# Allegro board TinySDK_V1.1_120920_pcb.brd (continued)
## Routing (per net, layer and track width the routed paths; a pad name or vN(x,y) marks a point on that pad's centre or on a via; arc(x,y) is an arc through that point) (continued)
GND_EARTH: length 13.6
  TOP w0.559: LAN1.8 165.07,21.21 ; 165.07,21.21 165.05,21.21 163.7,19.86 ; 165.07,21.21 172.09,21.21 173.23,22.35 173.23,23.44 C21.2
VBAT: length 7.7
  TOP w0.508: BAT1.1 66.39,36.58 D1.2 64.08,36.68 R11.1
VDD_3.3V: length 869
  TOP w0.254: 62.99,80.52 62.74,80.77 U7.3 ; 167.75,38.5 167.76,38.48 U4.30 ; U4.23 173.32,34.63 173.57,34.89 ; U4.42 162.18,32.63 162.05,32.77 ; U7.9 63.24,77.48
  TOP w0.508: 62.99,80.52 64.39,80.52
  TOP w0.559: v1(157.99,28.96) 157.99,28.7 154.69,25.4 FB2.1 ; R60.1 v1(75.46,88.77) ; 18.01,48.13 R39.2 v1(16.89,48.13) ; 18.01,40.51 R66.1 v1(16.89,40.51) ; R23.1 v1(66.32,88.77) ; CON8.39 41.25,75.54 v1(41.66,75.95) 42.05,75.55 CON8.41 ; v1(144.02,69.6) 144.39,69.6 144.4,69.59 v1(148.98,69.59) ; v1(144.02,69.6) 144.02,70.87 v1(143.89,70.99) ; v1(144.02,69.6) 144.02,69.22 144.15,69.09 v1(144.15,64.9) v1(144.15,61.34) ; v1(88.9,45.72) 89.66,46.48 C28.1 89.92,47.37 90.44,47.89 91.81,47.89 92.2,47.5 U5.8 ; 63.24,77.48 63.25,77.47 63.25,75.82 C67.1 66.17,75.56 67.18,76.58 67.18,79.88 66.55,80.52 C62.2 ; R32.2 129.29,38.99 128.91,39.37 v1(128.91,39.62) 128.91,39.88 129.54,40.51 R127.2 ; v1(16.89,42.04) R65.1 18.01,42.04 ; v1(16.89,46.61) R40.2 18.01,46.61 ; CON8.52 46.45,84.33 46.45,84.33 47.24,84.33 v1(48.13,83.44) ; v1(127.76,21.08) 128.14,20.7 R49.2 ; U2.4 28.22,20.73 21.46,13.97 R4.1 ; R21.1 173.86,29.18 v1(173.48,29.57) ; v1(173.74,36.96) 174.24,36.45 C16.1 175.01,36.32 173.57,34.89 ; R10.1 v1(99.31,49.28) v1(99.31,46.48) 99.31,42.04 v1(97.41,40.13) ; R31.2 137.01,40.51 R128.2 v1(137.03,41.78) ; R14.2 v1(70.89,88.77) ; 18.01,45.09 R43.1 v1(16.89,45.09) ; v1(160.27,28.83) 160.27,28.96 160.3,28.98 R20.1 ; R34.1 v1(72.42,88.77) ; CON8.24 35.25,85.09 v1(35.25,85.09) ; C17.1 168.78,39.75 170.69,41.66 v1(170.69,43.05) ; C17.1 167.64,39.75 v1(167.13,40.26) ; C17.1 168.66,39.5 167.75,38.59 167.75,38.5 ; R13.2 v1(67.84,88.77) ; v1(62.27,93.94) 62.27,91.27 R27.1 v1(63.27,88.77) ; v1(47.12,29.84) 45.85,28.57 C68.1 45.72,26.92 43.05,26.92 ; FB5.1 151.51,40.39 v1(151.76,40.13) ; R35.2 v1(16.89,51.18) ; R133.2 v1(144.91,41.78) ; 162.05,32.77 161.35,33.46 v1(161.35,34.86) 160.91,35.31 C18.1 160.15,35.43 160.15,36.7 C15.1 161.04,38.86 v1(160.78,39.12) 160.53,39.12 159.92,39.73 R5.2 ; v1(68.58,33.27) 68.48,33.17 D1.1 ; R131.2 v1(141.86,41.78) ; R30.1 63.88,83.44 65.66,81.66 C62.2 ; 23.25,84.7 23.25,84.7 CON8.2 ; 23.25,84.7 23.25,83.19 ; 23.25,84.7 22.86,85.09 22.35,85.09 v2(21.84,85.6) ; J1.2 96.77,117.32 R118.2 ; C62.2 64.39,80.52 ; R28.1 v1(69.37,88.77) ; 18.01,43.56 R64.1 v1(16.89,43.56) ; R129.2 v1(140.34,41.78) ; R126.2 127.13,37.47 v1(126.75,37.08) 126.95,36.88 FB1.1 ; R18.2 v1(73.94,88.77) ; 18.01,49.66 R37.2 v1(16.89,49.66) ; R132.2 v1(143.38,41.78) ; R9.1 v1(99.31,50.8) ; R12.2 v1(64.8,88.77) ; R19.2 v1(76.99,88.77)
  TOP w0.762: J1.2 99.06,115.32 100.33,114.05 102.62,114.05 108.03,119.46 CON6.1 ; 50.17,82.3 50.17,81.7 D4.1 53,77.56 54.36,76.2 57.02,76.2 57.66,75.56 C67.1
  TOP w1.016: v1(48.13,83.44) 48.13,83.19 49.02,82.3 50.17,82.3 52.96,85.09 C79.1 v1(51.05,85.72) ; v1(78.49,116.46) 78.59,116.35 R108.2 R107.2 R134.2 R114.2 R119.2 61.21,107.57 54.3,100.65 54.3,97.58 SDIO.1 55.59,93.8 R75.2
  TOP w1.524: v2(32.51,29.21) C11.1 C10.1 28.24,30.91 28.24,29.04 28.22,29.02 U2.2 U2.4 ; v2(21.84,85.6) 21.84,89.28 20.45,90.68 v2(15.37,90.68)
  BOTTOM w0.559: 143.38,40.79 v1(143.38,41.78) ; v1(143.89,70.99) R73.2 R72.2 ; 140.34,40.92 v1(140.34,41.78) ; R71.2 R42.2 v1(144.15,64.9) ; 144.91,40.79 v1(144.91,41.78) ; v1(144.02,69.6) 144.15,69.47 R41.2 ; 137.03,40.79 v1(137.03,41.78) ; C27.1 147.34,67.94 v1(148.98,69.59) CON10.4 ; 141.9,40.79 141.86,40.83 v1(141.86,41.78) ; v1(170.69,43.05) 170.69,42.93 172.21,41.4 172.21,38.48 v1(173.74,36.96) 174.14,36.55 174.14,30.22 v1(173.48,29.57) ; v1(167.13,40.26) 165.99,39.12 v1(160.78,39.12) ; v1(35.25,85.09) 35.31,85.03 C144.1 ; 121.54,35.31 122.43,34.42 122.43,23.62 124.97,21.08 v1(127.76,21.08) ; R38.2 R74.2 144.27,61.47 v1(144.15,61.34) ; 128.91,39.24 v1(128.91,39.62) ; v1(161.35,34.86) 160.27,33.78 v1(160.27,28.83) 158.12,28.83 v1(157.99,28.96) ; v1(99.31,46.48) 89.66,46.48 v1(88.9,45.72) ; v1(63.27,88.77) v1(64.8,88.77) v1(66.32,88.77) v1(67.84,88.77) v1(69.37,88.77) v1(70.89,88.77) v1(72.42,88.77) v1(73.94,88.77) v1(75.46,88.77) v1(76.99,88.77) ; v1(62.27,93.94) 61.89,94.32 57.56,94.32 SDIO.1 ; C148.1 46.61,83.44 v1(48.13,83.44) ; v1(99.31,49.28) v1(99.31,50.8) ; C145.1 v1(41.66,75.95)
  BOTTOM w1.016: SDIO.1 55.44,96.44 51.78,96.44 51.05,95.72 v1(51.05,85.72) ; 108.16,126.62 80.39,126.62 78.99,125.22 78.99,116.97 v1(78.49,116.46) ; 108.16,126.62 120.78,126.62 127.64,119.76 130.94,119.76 132.67,121.5 W1.2 133.1,122.19 133.92,123.01 133.92,123.01 137.4,126.49 168.78,126.49 175.9,119.38 175.9,99.06 178.38,96.57 178.38,79.32 175.64,76.58 175.64,65.15 171.45,60.96 166.75,60.96 158.12,69.59 CON10.4 ; 108.16,126.62 108.03,126.49 CON6.1
  BOTTOM w1.524: v2(21.84,85.6) 21.84,85.09 C142.1 25.85,83.57 25.92,83.49 27.02,83.49 27.09,83.57 C144.1 41.15,83.57 ; v1(41.66,75.95) 41.66,83.06 41.15,83.57 ; 41.15,83.57 C148.1 ; v1(160.78,39.12) 159.77,40.13 v1(151.76,40.13) 149.22,40.13 148.56,40.79 140.46,40.79 140.08,41.17 137.41,41.17 137.03,40.79 131.2,40.79 130.07,39.66 129.32,39.66 v1(126.75,37.08) 123.32,37.08 121.54,35.31 111.92,35.31 107.1,40.13 v1(97.41,40.13) 82.04,40.13 75.18,33.27 v1(68.58,33.27) 59.94,33.27 56.52,29.84 v1(47.12,29.84) 33.15,29.84 v2(32.51,29.21) 31.37,28.07 27.47,28.07 27.34,27.94 24.77,27.94 22.35,30.35 22.35,33.32 22.25,33.52 22.1,34.03 20.45,35.69 20.45,36.96 v1(16.89,40.51) v1(16.89,42.04) v1(16.89,43.56) v1(16.89,45.09) v1(16.89,46.61) v1(16.89,48.13) v1(16.89,49.66) v1(16.89,51.18) 16.89,56.26 17.78,57.15 17.78,60.45 19.94,62.61 19.94,68.45 15.37,73.03 v2(15.37,90.68)
VDD_5V: length 573
  TOP w0.305: LCD2.2 92.05,63.48 91.82,63.25 91.82,62.48 93.47,60.83 v1(93.47,59.69) ; LCD2.1 94.23,62.98 94.74,62.47 v1(94.74,59.69)
  TOP w0.559: 165.86,116.97 167.26,115.57 167.26,115.57 167.14,115.7
  TOP w1.016: USBH2.1 148.84,116.21 C96.1 ; v1(121.41,21.46) 121.41,28.19 125.58,32.36 FB3.1 ; USBH3.1 116.21,13.59 C97.1 v1(114.05,17.15) ; USBH1.1 167.14,115.7 C73.1
  TOP w1.27: C8.1 19.3,27.94 C9.1 24.13,29.46 25.02,29.46 25.96,28.52 U2.3 ; TINY210.A1 116.69,91 114.34,88.65 108.71,88.65 108.68,88.61 108.15,88.61 105.28,85.74 103.27,85.74 97.84,80.31 v2(97.84,80.31)
  TOP w2.54: 18.84,22.56 18.54,22.86 C8.1 18.54,30.35 v2(18.41,30.48) 18.41,32.26 v1(19.88,33.72) v2(22.73,36.58) v1(24.51,38.35) ; 18.84,22.56 19.31,22.1 CON5.1 ; 18.84,22.56 11.89,22.56 7.31,17.98 S1.2
  BOTTOM w0.305: 29.31,68.86 29.08,69.09 28.81,68.82 LCD3.1 28.81,66.06 29.08,65.79 29.31,66.02 LCD3.2 29.31,68.86 ; 29.31,47.98 28.96,47.62 28.81,47.77 LCD1.1 28.81,53.2 29.08,53.47 29.31,53.24 LCD1.2 29.31,47.98
  BOTTOM w0.559: v1(24.51,38.35) 24.51,41.02 28.32,44.83 28.32,46.99 28.96,47.62 ; BUZZER1.1 9.65,103.5 16.64,96.52 16.64,73.94 19.71,70.87 27.3,70.87 29.08,69.09 ; 29.08,53.47 29.08,65.79
  BOTTOM w0.762: v1(19.88,33.72) 19.88,34.37 19.5,34.74 19.05,34.74 18.67,35.12 18.67,36.32 15.88,39.12 15.24,39.12 14.1,40.26 14.1,52.37 LCD4.1 LCD4.2
  BOTTOM w1.016: 72.64,21.84 72.69,21.79 CON2.5 ; 72.64,21.84 87.76,21.84 ; 72.64,21.84 61.59,21.84 ; 87.76,21.84 92.96,21.84 96.14,18.67 112.53,18.67 v1(114.05,17.15) 114.05,17.14 120.4,17.14 121.41,18.16 v1(121.41,21.46) ; 87.76,21.84 87.89,21.71 CON1.3 ; 50.55,21.84 50.29,21.59 CON4.3 ; 50.55,21.84 46.15,21.84 45.52,22.48 27.57,22.48 19.57,30.48 v2(18.41,30.48) ; 50.55,21.84 61.59,21.84 ; CON3.3 61.47,21.72 61.59,21.84
  BOTTOM w1.27: v2(97.84,80.31) 98.04,80.11 98.04,73.96 98.76,73.25 98.76,70.92 102.87,66.8 102.87,60.45 101.98,59.56 96.58,59.56 96.38,59.77 95.76,59.77 95.63,59.64
  BOTTOM w1.524: USBH2.1 148.08,116.97 148.08,121.95 147.4,122.63 ; 147.4,122.63 136.22,122.63 131.44,117.86 126.87,117.86 125.09,116.08 125.09,115.95 121.79,112.65 121.79,99.95 118.62,96.77 118.62,91.38 TINY210.A1 ; 147.4,122.63 160.2,122.63 USBH1.1 ; v2(22.73,36.58) 23.68,35.63 23.68,34.88 23.7,34.86 23.72,34.61 23.85,34.15 24.07,33.74 24.07,33.46 25.02,32.51 56.01,32.51 65.15,41.66 78.49,41.66 94.11,57.28 94.11,59.69 ; 94.11,59.69 v1(94.74,59.69) 94.79,59.64 95.63,59.64 ; 94.11,59.69 v1(93.47,59.69)
VDD_AUDIO_A3.3V: length 21.1
  TOP w0.254: 142.75,30.99 142.37,30.99 142.09,31.27 U6.32
  TOP w0.508: C31.1 145.69,30.45 145.69,28.92 146.48,28.14 148.16,28.14 148.21,28.19 148.3,28.19 v1(148.34,28.23) 148.46,28.36 C32.1 ; FB2.2 152.91,24.64 151.76,23.5 v1(148.59,23.5)
  TOP w0.559: 142.75,30.99 143.13,31.37 C31.1
  BOTTOM w0.508: v1(148.34,28.23) 148.39,28.18 148.39,23.7 v1(148.59,23.5)
VDD_AUDIO_D3.3V: length 12.3
  TOP w0.305: U6.10 141.59,37.19 141.86,37.47 143.26,37.47 143.51,37.21 143.51,36.45 143.1,36.04 U6.8
  TOP w0.559: 143.51,37.21 144.15,37.21 145.12,38.19 145.53,38.19 145.57,38.23 145.8,38.23 146.56,38.99 C50.1 147.96,39.24 C54.1 FB5.2
VDD_AUDIO_SPK: length 23.8
  TOP w0.254: v1(136.65,33.76) 136.71,33.76 136.99,34.04 U6.21
  TOP w0.305: 138.94,30.99 139.08,31.13 U6.26
  TOP w0.508: 138.94,30.99 138.43,30.48 137.79,30.48 v1(137.54,30.23) 136.91,30.23 136.47,29.79 135.21,29.79 134.98,29.56 134.98,29.55 134.37,28.94 C29.1
  TOP w0.559: v1(132.64,30.12) 132.84,29.92 C30.1 134.11,28.83 C29.1 ; v1(128.14,30.73) 128.41,31 128.41,31.93 128.47,32 FB3.2 128.48,32.36 FB1.2
  BOTTOM w0.508: v1(136.65,33.76) 136.78,33.76 137.97,32.57 137.97,30.66 v1(137.54,30.23)
  BOTTOM w0.559: v1(128.14,30.73) 128.32,30.91 131.85,30.91 v1(132.64,30.12)
VDD_CAM_1.8V: length 100.6
  TOP w0.203: 146.43,102.87 U9.20
  TOP w0.406: C106.2 144.67,101.22 145.32,101.87 145.43,101.87 146.43,102.87
  TOP w0.508: v1(117.6,108.46) 118.36,107.7 133.73,107.7 138.13,103.3 142.57,103.3 L8.1 143,102.74 C106.2
  BOTTOM w0.305: 118.24,73.15 118.36,73.03 119.97,73.03 TINY210.C19
  BOTTOM w0.508: CAMERA.19 100.68,122.55 100.69,122.56 103.38,122.56 106.55,119.38 110.36,119.38 117.47,112.27 117.47,108.58 v1(117.6,108.46) 117.6,106.76 115.95,105.11 115.95,101.47 113.54,99.06 113.54,88.19 117.17,84.56 117.17,74.22 118.24,73.15
VDD_CAM_2.5V: length 73.7
  TOP w0.381: CAMERA.18 98.67,124.47 99.69,123.45 99.69,122.14 99.69,122.14 v1(99.69,121.67)
  BOTTOM w0.381: CAMERA.18 99.69,123.53 99.69,122.14 99.69,122.14 v1(99.69,121.67)
  BOTTOM w0.508: TINY210.C18 116.4,72.6 116.4,84.34 112.74,88 112.74,99.4 115.25,101.92 115.25,105.4 116.59,106.73 116.59,112.01 115.25,113.35 110.7,117.9 109.92,118.68 106.26,118.68 103.44,121.51 99.85,121.51 v1(99.69,121.67)
VDD_CCD_3.3V: length 109.4
  TOP w0.254: U9.10 151.87,107.93 152.02,108.08
  TOP w0.508: v1(148.46,94.23) 149.22,95 R145.1
  TOP w0.559: v1(158.5,107.44) 158.37,107.31 R146.1 ; 152.4,108.46 152.02,108.08 ; 152.4,108.46 v1(153.16,107.7) ; 152.4,108.46 C105.2 ; R144.2 143.28,95.35 v1(142.62,96.01) 142.49,96.14 142.49,98.81 143.1,99.42 R143.1 143.13,99.57 144.27,98.42 146.05,98.42 147.32,99.69 v1(147.32,100.18) ; v1(106.81,94.87) 113.28,94.87 115.22,96.8 v1(120.52,96.8)
  BOTTOM w0.508: v1(148.46,94.23) 148.23,94.46 144.17,94.46
  BOTTOM w0.559: v1(147.32,100.18) 148.82,101.68 152.9,101.68 153.24,102.01 153.24,103.45 154.05,104.27 154.05,106.43 153.8,106.68 ; 144.17,94.46 v1(142.62,96.01) 141.78,96.85 136.73,96.85 136.7,96.88 136.68,96.85 124.88,96.85 124.39,97.35 122.09,97.35 121.49,96.75 120.58,96.75 v1(120.52,96.8) ; v1(158.5,107.44) 157.73,106.68 153.8,106.68 ; 153.24,107.24 153.16,107.31 v1(153.16,107.7) 153.24,107.62 153.24,107.24 ; 153.24,107.24 153.8,106.68 ; J1.1 96.78,115.31 98.02,114.07 102.39,114.07 106.9,109.56 107.46,109.56 108.93,108.09 108.93,104.74 106.81,102.62 v1(106.81,94.87)
VDD_CMOS_3.3V: length 8.1
  TOP w0.762: CAMERA.17 98.67,121.03 100.78,118.92 J1.3
VDD_IN: length 16.7
  TOP w2.032: S1.3 4.05,15.02 9.18,15.02 CON5.4 12.3,16.92 12.3,16.53 15.1,13.73 15.1,11.01 CN1.1
VDD_RTC_AP: length 69.1
  TOP w0.33: TINY210.B4 120.36,44.36 120.36,38.14 v1(120.9,37.59)
  TOP w0.508: R11.2 v1(65.56,35.03)
  BOTTOM w0.381: v1(120.9,37.59) 120.51,37.99 110.86,37.99 107.31,41.53 80.52,41.53 77.52,38.53 69.06,38.53 v1(65.56,35.03)
AUDIO_XI2SCDCLK0: length 12
  TOP w0.203: TINY210.B30 145.8,43.8 145.8,39.98 R133.1 143.79,37.97 141.6,37.97 141.09,37.45 U6.11
AUDIO_XI2SLRCK0: length 18.2
  TOP w0.203: TINY210.B31 148.14,47.86 144.64,47.86 144.02,47.24 144.02,44.2 142.62,42.8 142.62,39.75 141.96,39.09 R131.1 141.61,39.09 140.88,38.37 140.47,38.37 140.08,37.98 U6.13
AUDIO_XI2SSCLK0: length 13.9
  TOP w0.203: U6.12 140.59,37.51 141.44,38.37 142.41,38.37 143.13,39.09 R132.1 143.87,39.09 144.15,39.37 144.15,42.92 145.86,44.64 145.86,45.86 TINY210.B29
AUDIO_XI2SSDI0: length 25.8
  TOP w0.203: U6.16 138.58,37.18 138.43,37.34 137.41,37.34 137.03,37.72 R128.1 137.72,39.65 137.72,39.83 137.79,39.91 137.79,42.55 139.86,44.61 139.86,47.79 140.94,48.87 149.13,48.87 TINY210.B33
AUDIO_XI2SSDO0_0: length 24
  TOP w0.203: TINY210.B32 150.11,46.11 150.11,47.12 148.97,48.26 142.49,48.26 141.86,47.63 141.86,44.33 139.64,42.1 139.64,40.09 140.34,39.39 R129.1 139.58,38.34 U6.14
CAM_A_RESET: length 154.1
  TOP w0.203: v1(99.82,107.95) 99.82,108.08 103.48,111.73 104.78,111.73 105.31,112.27 106.97,112.27 111.92,117.22 130.3,117.22 138.81,108.71 146.94,108.71 148.21,109.98 155.07,109.98 155.83,109.22 C113.2 155.83,107.34 R146.2 155.19,106.71 155.19,105.16 154.4,104.37 U9.8
  BOTTOM w0.203: TINY210.C4 118.48,56.52 117.55,56.52 108.94,65.13 108.94,80.18 104.28,84.84 104.28,95.47 103.14,96.61 103.14,101.92 103.14,103.27 101.35,105.06 101.35,106.72 100.27,107.79 100.2,107.79 100.13,107.86 99.91,107.86 v1(99.82,107.95) 99.19,107.95 85.6,121.54 85.6,123.62 CAMERA.4
CAM_SCL0: length 132
  TOP w0.203: R140.1 132.09,107.15 112.3,107.15 109.41,110.05 107.89,110.05 107.31,110.62 104.65,110.62 100.53,106.5 v1(100,106.5)
  BOTTOM w0.203: CAMERA.2 83.69,123.53 83.69,122.17 86.45,119.42 86.5,119.42 97.93,107.99 97.93,107.94 99.13,106.74 99.77,106.74 v1(100,106.5) 100.44,106.06 100.44,104.15 102.35,102.24 102.35,96.28 102.81,95.82 103.49,95.14 103.49,84.52 108.13,79.88 108.13,64.79 118.92,54 TINY210.C2
CAM_SDA0: length 141.9
  TOP w0.203: v1(99.78,105.28) 99.9,105.28 104.73,110.11 107.06,110.11 110.8,106.37 131.17,106.37 134.25,103.29 134.25,102.27 140.86,95.66 141.83,95.66 142.88,94.61 144.42,94.61 R141.1
  BOTTOM w0.203: TINY210.C1 120.09,53.09 118.62,53.09 107.72,63.99 107.72,79.73 104.3,83.15 103.1,84.35 103.1,94.98 102.65,95.42 101.96,96.12 101.96,101.5 99.78,103.67 v1(99.78,105.28) 99.78,105.53 94.75,110.56 94.75,110.57 93.93,111.39 93.92,111.39 86.72,118.59 86.72,118.64 86.33,119.02 86.29,119.02 85.74,119.57 82.76,122.55 CAMERA.1
CAMERA_A_GPIO2: length 85
  BOTTOM w0.203: CAMERA.3 84.67,121.91 99.29,107.29 100.22,107.29 100.84,106.67 100.84,105.01 102.75,103.1 102.75,96.44 103.89,95.3 103.89,84.68 108.53,80.03 108.53,64.96 118.41,55.09 120.09,55.09 TINY210.C3
CCD_AGND: length 38.4
  TOP w0.254: U9.31 151.87,100.22 v1(151.26,100.84) ; v1(155.32,104.27) 154.92,103.87 U9.7 ; U9.3 v1(155.31,101.87)
  TOP w0.508: C111.1 152.02,95.25 152.91,94.36 154.05,94.36 C112.1
  TOP w0.559: C112.1 C107.1 157.48,94.49 160.53,94.49 161.07,93.94 165.95,93.94 C104.2 167.39,95.38 v1(168.53,95.38) ; v1(170.94,113.16) 171.07,113.03 L9.1 172.09,112.01 v1(171.83,111.76) ; v1(163.07,98.17) 161.93,97.03 C65.2 ; R51.2 163.7,97.28 v1(164.21,97.79) ; C109.2 v1(158.12,100.2) ; C108.2 v1(158.37,105.28)
  BOTTOM w0.559: 171,103.53 AVIN.3 ; AVIN.3 171,107.44 ; AVIN.3 169.04,105.48
CCD_SCL: length 8.4
  TOP w0.203: U9.21 146.63,102.37 145.41,101.15 145.41,101.14 145.26,100.98 145.26,100.68 145.14,100.55 145.14,99.9 144.8,99.57 R143.2 143.92,100.33 142.01,100.33 R140.2
CCD_SDA: length 10.1
  TOP w0.203: R144.1 R141.2 145.31,96.93 146.05,97.66 146.81,97.66 147.19,98.04 147.45,98.04 148.15,98.74 148.15,99.76 148.97,100.58 148.97,101.35 148.45,101.87 U9.22
DM2-: length 221.7
  TOP w0.203: R110.1 120.17,19.23 120.17,20.29 116.45,24.02 116.45,47.12 119.06,49.73 128.97,49.73 131.66,52.43 158.33,52.43 168.71,62.8 168.71,64.61 v1(168.29,65.02) ; v1(168.78,92.68) 168.5,92.68 168.39,92.58 160.08,92.58 159.58,93.09 156.83,93.09 156.32,92.58 150.5,92.58 150.11,92.96 140.58,92.96 128.77,104.78 112.01,104.78 108.97,101.73 99.69,101.73 98.02,103.4 97.2,103.4 96.55,104.06 96.55,104.98 97.91,106.34 97.91,107.4 97.92,107.41 97.92,108.83 96.78,109.97 95.33,109.97 94.58,110.72 93.14,110.72 93.1,110.76 U11.3
  BOTTOM w0.203: v1(168.29,65.02) 168.71,65.44 168.71,83.49 170.69,85.47 173.1,85.47 174.75,87.12 174.75,88.03 174.14,88.64 174.14,91.36 174.94,92.16 174.94,92.51 174.54,92.91 169.01,92.91 v1(168.78,92.68)
DM3-: length 78.7
  TOP w0.203: U11.6 93.72,112.26 94.3,112.84 98.43,112.84 99.14,112.13 104.62,112.13 105.33,112.84 106.98,112.84 112.09,117.94 130.64,117.94 137.31,111.27 139.36,109.22 146.56,109.22 147.83,110.49 157.73,110.49 158.75,109.47 161.04,109.47 161.65,110.08 161.65,110.95 R89.1
DM4-: length 60.8
  TOP w0.203: R95.1 145.14,111.48 143.89,110.23 140.91,110.23 131.46,119.67 111.05,119.67 104.29,112.92 99.48,112.92 98.6,113.79 94.12,113.79 93.63,113.3 93.62,113.3 93.57,113.26 U11.8
DM9000_RX+: length 17.1
  TOP w0.203: U4.3 165.76,26.82 v1(165.23,26.29) 165.23,25.64 R26.1
  BOTTOM w0.203: v1(165.23,26.29) 165.51,26.01 165.51,25.13 164.46,24.08 162.89,24.08 159.64,20.83 159.64,19.48 159.03,18.86 158.89,18.86 157.35,17.32 ; 157.35,17.32 157.35,17.32 ; 157.35,17.32 LAN1.3
DM9000_RX-: length 16.5
  TOP w0.203: U4.4 166.26,26.31 v1(166.24,26.29) 165.97,26.02 R29.1
  BOTTOM w0.203: 161.16,19.86 161.16,19.43 ; 161.16,19.43 161.16,19.43 LAN1.6 ; 161.16,19.43 161.16,18.99 160.83,18.67 160.53,18.67 160.1,19.1 160.1,20.64 163.08,23.62 164.64,23.62 165.96,24.94 165.96,26.01 v1(166.24,26.29)
DM9000_TX+: length 32.7
  TOP w0.203: U4.7 167.76,26.28 v1(167.64,26.16) 167.89,25.91 167.89,25.51 R24.1
  BOTTOM w0.203: v1(167.64,26.16) 167.77,26.04 167.77,19.19 163.38,14.8 155.39,14.8 153.24,16.95 153.24,18.11 153.8,18.67 155.07,18.67 155.45,18.29 155.45,17.96 154.81,17.32 LAN1.1
DM9000_TX-: length 35.4
  TOP w0.203: R25.1 168.4,25.35 168.4,25.91 v1(168.66,26.16) 168.26,26.55 U4.8
  BOTTOM w0.203: LAN1.2 156.08,19.83 156.08,19.05 155.83,18.8 155.58,18.8 155.26,19.13 153.61,19.13 152.78,18.3 152.78,16.76 155.2,14.34 163.57,14.34 168.22,19 168.22,25.73 v1(168.66,26.16)
DP2+: length 222.5
  TOP w0.203: U11.4 93.1,111.26 93.13,111.24 93.27,111.24 93.33,111.18 94.77,111.18 95.52,110.43 96.97,110.43 98.37,109.02 98.37,107.22 98.36,107.21 98.36,106.15 97,104.79 97,104.25 97.39,103.86 98.21,103.86 99.88,102.18 108.78,102.18 111.82,105.23 128.96,105.23 140.77,93.42 150.3,93.42 150.68,93.04 156.13,93.04 156.64,93.55 159.77,93.55 160.27,93.04 168.2,93.04 168.51,93.34 168.53,93.34 v1(168.78,93.6) ; R112.1 120.63,19.23 120.63,20.48 116.9,24.2 116.9,46.93 119.25,49.28 129.16,49.28 131.85,51.97 158.52,51.97 169.16,62.61 169.16,64.61 v1(169.58,65.02)
  BOTTOM w0.203: v1(169.58,65.02) 169.16,65.44 169.16,83.3 170.88,85.01 173.29,85.01 175.21,86.93 175.21,87.99 175.86,88.64 175.86,91.4 175.39,91.87 175.39,92.7 174.73,93.37 169.01,93.37 v1(168.78,93.6)
DP3+: length 77.9
  TOP w0.203: R90.1 161.19,110.95 161.19,110.39 160.77,109.97 158.96,109.97 157.94,110.99 147.62,110.99 146.35,109.72 139.53,109.72 130.91,118.34 111.65,118.34 106.6,113.28 105.22,113.28 104.45,112.52 99.32,112.52 98.56,113.28 94.17,113.28 93.79,112.91 93.78,112.91 93.63,112.76 U11.7
DP4+: length 59.3
  TOP w0.203: U11.9 93.44,113.76 93.93,114.25 98.79,114.25 99.67,113.37 104.1,113.37 110.86,120.13 131.65,120.13 141.1,110.69 143.33,110.69 143.77,111.13 R97.1
EARPHONE_DETECT: length 51.9
  TOP w0.203: v1(127.13,31.24) 126.75,30.86 125.22,30.86 122.43,28.07 122.43,21.59 126.62,17.4 C35.1 126.64,17.25 R49.1 130.3,15.09 130.3,11.43 132.46,9.27 SPK1.2 ; v1(137.92,38) 138.11,38.19 138.11,39.67 138.81,40.36 R92.1
  BOTTOM w0.203: v1(137.92,38) 137.92,37.72 137.29,37.08 130.43,37.08 129.92,36.58 129.92,34.72 130.2,34.44 130.2,33.89 127.55,31.24 v1(127.13,31.24)
HS_IND/CFG_SEL1: length 6.8
  TOP w0.203: U11.25 84.12,110.76 R115.2 83.67,110.61 82.98,111.31 80.86,111.31 R134.1
LANLED: length 41.4
  TOP w0.203: U4.39 164.87,34.14 165.23,33.78 165.23,32.13 166.78,30.58 168.96,30.58 169.17,30.79 169.87,30.79 170.81,29.84 170.81,29.08 173,26.9 173,26.16 173.25,25.91 173.86,25.91 175.12,24.65 175.12,23.79 173.98,22.64 173.98,20.98 171.7,18.71 171.7,14.43 163.34,6.07 LAN1.11
LINKLED: length 38
  TOP w0.203: v1(164.68,34.8) 164.52,34.63 U4.38 ; v1(162.56,28.72) 162.28,28.72 162.02,28.45 161.52,27.95 158.71,27.95 155.77,25 155.77,23.01 153.81,21.06 153.81,15.22 156.2,12.84 156.2,9.77 155.17,8.73 155.17,6.48 155.17,6.47 LAN1.10
  BOTTOM w0.203: v1(164.68,34.8) 163.7,33.82 163.7,29.86 v1(162.56,28.72)
LOCAL_PWR: length 5
  TOP w0.203: U11.28 87.28,108.24 87.19,108.14 86.47,108.14 86.38,108.23 85.83,108.23 84.76,107.16 84.76,106.83 R111.2
M_NRESET: length 75.3
  TOP w0.203: v1(132.33,50.06) 176.98,50.06 178.73,48.32 178.73,36.41 RST.1
  BOTTOM w0.203: TINY210.B3 122.74,48.74 131.24,48.74 132.33,49.84 v1(132.33,50.06)
MICBIAS: length 8.2
  TOP w0.254: U6.1 144.57,32.54 144.84,32.27 145.78,32.27 C60.1
  TOP w0.279: R59.2 149.2,32.16 C59.2 146.69,31.37 C60.1
NET_AVDD25: length 32.1
  TOP w0.254: U4.2 165.26,27.29 165.1,27.13 164.7,27.13 164.59,27.02 ; 168.99,26.97 168.76,27.2 U4.9
  TOP w0.559: 168.99,26.97 169.88,26.97 169.92,26.97 171.03,25.86 171.03,25.74 171.69,25.08 ; 164.59,27.02 163.59,27.02 v1(163.58,27.03) 163.58,27.03 163.57,27.02 162.78,27.02 161.78,26.02 C24.1 161.15,24.99 C22.1 158.62,22.46 158.62,19.83 LAN1.4 158.62,18.56 LAN1.5 ; 171.69,25.08 C23.1 ; 171.69,25.08 171.69,25.38 v1(172.34,26.04)
  BOTTOM w0.559: v1(163.58,27.03) 165,28.45 168.15,28.45 169.62,26.97 169.92,26.97 170.86,26.04 v1(172.34,26.04)
NRESET: length 7.2
  TOP w0.203: U11.26 85.12,110.26 C83.1 83.7,109.09 83.14,109.65 83.14,109.65 82.99,109.8 80.88,109.8 R114.1
NWAIT: length 6.6
  TOP w0.203: TINY210.B41 159,46.44 158.09,45.53 158.09,44.1 159.38,42.8 R5.1
OM1: length 82.7
  TOP w0.203: v1(130.94,49.4) 131.44,48.9 132.97,48.9 133.34,49.26 176.67,49.26 177.93,48.01 177.93,37.42 175.72,35.22 174.76,34.25 174.76,30.3 176.66,28.4 R1.2
  BOTTOM w0.203: v1(130.94,49.4) 130.76,49.23 122.3,49.23 121.48,48.4 120.97,48.4 119.57,47 TINY210.B1
RBIAS: length 10.2
  TOP w0.203: R121.1 94.24,103 95.25,104.01 95.25,106.25 95.07,106.43 95.07,107.11 95.06,107.13 95.06,107.51 94.74,107.82 91.19,107.82 90.78,108.23 U11.35
RSRXD0: length 45.9
  TOP w0.203: 74.85,11.13 74.86,11.12 COM0.2
  TOP w0.279: 43.05,23.11 41.4,23.11 40.77,22.48 40.77,16.13 43.31,13.59 72.39,13.59 74.85,11.13
RSRXD3: length 9.4
  TOP w0.279: U8.8 38.73,18.03 39.12,17.65 39.12,10.74 COM3.2
RSTXD0: length 53.3
  TOP w0.279: 43.05,24.38 40.77,24.38 40.13,23.75 40.13,15.62 42.67,13.08 71.75,13.08 73.66,11.18 73.66,9.27 74.04,8.89 76.2,8.89 COM0.3
RSTXD3: length 11.4
  TOP w0.279: COM3.3 41.4,13.21 39.62,14.99 39.62,18.41 38.73,19.3 U8.7
SCL/CFG_SEL0: length 7.2
  TOP w0.203: R107.1 80.86,112.84 83.51,112.84 83.97,112.37 R116.2 84.86,111.26 U11.24
SDA: length 9.7
  TOP w0.203: R108.1 80.16,115.6 80.77,116.2 82.96,116.2 R117.2 85.08,115.19 85.59,114.68 85.59,112.52 85.85,112.26 U11.22
SPK_OUT_LN: length 21.6
  TOP w0.203: U6.23 137.56,33.04 137.16,32.64 C38.1 134.65,31.9 132.74,31.9 131.38,30.54 131.38,25.84 131.65,25.58 132.46,24.77 136.23,24.77 137.65,23.35 137.65,22.36 CON12.2
SPK_OUT_LP: length 22
  TOP w0.203: U6.25 138.58,31.52 138.18,31.11 135.76,31.11 C37.1 135.13,30.73 134.42,31.45 132.93,31.45 131.84,30.35 131.84,26.03 132.65,25.22 136.42,25.22 138.11,23.54 138.11,22.36 CON12.1
SPK_OUT_RN: length 29.2
  TOP w0.203: U6.19 137.22,35.04 136.45,35.81 C48.1 134.67,35.1 132.69,35.1 131.21,33.62 131.21,32.63 129.78,31.21 129.78,29.19 129.78,29.19 129.78,20.46 131.25,18.99 133.48,18.99 134.11,19.62 134.11,20.82 CON12.3
SPK_OUT_RP: length 27.1
  TOP w0.203: CON12.4 133.65,20.82 133.65,19.81 133.29,19.44 131.44,19.44 130.24,20.65 130.24,29 130.24,31.02 131.66,32.44 131.66,33.44 132.85,34.62 134.67,34.62 C47.1 135.94,33.35 135.94,33.35 136.26,33.03 136.92,33.03 137.43,33.54 U6.22
USB_D+: length 51.9
  TOP w0.203: R80.2 55.17,90.32 55.71,90.32 v1(56.13,89.9) ; v1(93.6,109.09) 93.6,109.1 93.6,109.73 93.07,110.26 U11.2
  BOTTOM w0.203: v1(56.13,89.9) 56.79,90.55 74.81,90.55 74.81,90.55 75.18,90.55 75.18,90.55 85.46,100.83 89.53,100.83 93.6,104.9 v1(93.6,109.09)
USB_D-: length 50.4
  TOP w0.203: R81.2 55.17,90.78 55.73,90.78 v1(56.13,91.19) ; U11.1 92.81,109.76 92.96,109.6 92.96,109.39 92.94,109.37 92.94,109.21 v1(92.7,108.96)
  BOTTOM w0.203: v1(92.7,108.96) 93.14,108.52 93.14,105.09 89.34,101.29 85.27,101.29 74.99,91.01 56.31,91.01 v1(56.13,91.19)
USIM_CLK: length 19.4
  TOP w0.203: v1(27.25,85.47) 27.25,85.47 CON8.12
  BOTTOM w0.203: v1(27.25,85.47) 32.3,85.47 33.27,86.44 33.27,90.81 C76.1 36,93.53 P1.3
USIM_DATA: length 41.4
  TOP w0.203: CON8.10 26.45,84.79 ; 26.45,84.79 26.45,84.79 26.45,83.19 ; 26.45,84.79 v1(26.47,84.81)
  BOTTOM w0.203: P1.6 36,98.75 37.21,97.54 37.21,93.75 36.32,92.86 C77.1 35.13,90.75 35.13,86.56 33.38,84.81 v1(26.47,84.81)
USIM_RST: length 19.6
  TOP w0.203: CON8.14 28.05,86.13 v1(28.05,86.13) 28.05,83.19
  BOTTOM w0.203: v1(28.05,86.13) 30.76,86.13 31.62,87 31.62,91.06 C78.1 33.46,92.89 P1.2
USIM_VCC: length 16.7
  TOP w0.203: v1(25.65,86.87) 25.65,86.87 CON8.8
  BOTTOM w0.203: P1.1 30.92,92.26 C75.1 29.72,91.06 29.72,88.01 28.57,86.87 v1(25.65,86.87)
W_DISABLE_N: length 25.1
  TOP w0.203: R75.1 52.81,93.09 50.16,93.09 46.61,89.53 37.47,89.53 35.05,87.12 35.05,86.49 33.65,85.08 33.65,84.2 33.65,84.2 CON8.20
WIFI0_PD_GPIO: length 113
  TOP w0.203: SDIO.11 64.8,95.49 R12.1 65.49,91.15 65.49,88.65 69.56,84.58 79.6,84.58 81.79,86.77 82.7,86.77 86.42,90.49 96.87,90.49 102.34,95.96 112.8,95.96 114.7,97.86 122.23,97.86 v1(122.56,98.18)
  BOTTOM w0.203: TINY210.A41 159.03,91.03 159.03,92.56 156.21,95.38 156,95.38 155.81,95.57 144.08,95.57 142.11,97.54 125.01,97.54 124.62,97.92 122.82,97.92 v1(122.56,98.18)
WIFI0_RESET_GPIO: length 121.5
  TOP w0.203: v1(124.69,98.58) 123.58,97.46 114.86,97.46 112.97,95.57 102.5,95.57 97.03,90.09 86.59,90.09 82.87,86.37 81.95,86.37 79.64,84.06 67.68,84.06 64.01,87.73 64.01,91.11 R27.2 63.27,94.64 64.64,96.02 64.64,97.33 SDIO.12
  BOTTOM w0.203: v1(124.69,98.58) 125.3,97.97 142.24,97.97 144.24,95.96 155.97,95.96 156.17,95.77 156.37,95.77 159.59,92.56 159.59,91.82 159.91,91.49 159.91,89.91 TINY210.A42
XADCAIN0: length 114.7
  TOP w0.203: TINY210.A39 157,90.71 156.14,89.84 156.14,86.49 152.23,82.59 151.69,82.04 140.84,82.04 140.47,82.41 v1(139.98,82.41) ; CON6.2 110.03,124.56 110.06,124.56 110.95,125.45 122.2,125.45 124.21,123.44 C64.1 127.1,125.19 W1.3
  BOTTOM w0.203: CON6.2 110.03,122.25 118.36,113.92 118.36,103.06 114.11,98.81 114.11,89.02 120.26,82.87 136.97,82.87 137.69,82.14 139.55,82.14 139.81,82.41 v1(139.98,82.41)
XADCAIN1: length 88.1
  TOP w0.203: TINY210.A40 157,86.8 152.62,82.42 151.85,81.65 139.81,81.65 138.86,82.59 v1(138.86,82.92)
  BOTTOM w0.203: CON6.3 112.03,120.81 118.76,114.08 118.76,102.7 114.56,98.5 114.56,89.2 120.5,83.26 138.52,83.26 v1(138.86,82.92)
XADCAIN6_YM: length 81.8
  TOP w0.203: v1(139.83,83.31) 139.93,83.21 142.77,83.21 144.78,85.22 151.51,85.22 155,88.71 TINY210.A38
  BOTTOM w0.203: CON6.4 114.55,122.16 114.55,118.84 119.15,114.25 119.15,102.53 115.4,98.79 115.4,89.15 120.86,83.69 139.45,83.69 v1(139.83,83.31)
XADCAIN7_YP: length 82.6
  TOP w0.203: TINY210.A37 154.75,91 153.92,90.17 153.92,88.27 151.32,85.67 144.59,85.67 142.88,83.95 v1(141.48,83.95)
  BOTTOM w0.203: CON6.5 116.03,122.38 115.06,121.41 115.06,118.89 119.55,114.41 119.55,102.37 115.8,98.62 115.8,89.31 120.91,84.2 139.95,84.2 140.21,83.95 v1(141.48,83.95)
XADCAIN8_XM: length 76.7
  TOP w0.203: v1(140.88,84.84) 142.49,84.84 143.72,86.06 151.08,86.06 153,87.98 TINY210.A36
  BOTTOM w0.203: v1(140.88,84.84) 140.72,84.67 120.99,84.67 116.19,89.47 116.19,98.46 119.94,102.21 119.94,114.57 119.3,115.21 119.3,121.38 118.95,121.73 118.95,121.76 CON6.6
XADCAIN9_XP: length 76.9
  TOP w0.203: TINY210.A35 153,90.77 152.14,89.91 152.14,87.87 150.72,86.45 142.71,86.45 v1(141.86,85.6)
  BOTTOM w0.203: CON6.7 120.03,121.05 119.89,120.9 119.89,115.18 120.33,114.73 120.33,102.04 116.59,98.3 116.59,89.64 121.16,85.06 139.93,85.06 140.46,85.6 v1(141.86,85.6)
XCICLKENB: length 82.6
  BOTTOM w0.203: CAMERA.5 86.67,121.1 99.11,108.66 100.04,108.66 101.74,106.97 101.74,105.22 103.53,103.43 103.53,102.73 103.53,97 104.67,95.86 104.67,85 109.35,80.33 109.35,65.3 117.56,57.09 120.09,57.09 TINY210.C5
XCIHREF: length 133
  TOP w0.203: v1(104.65,103) 104.78,102.87 108.66,102.87 111.76,105.97 131.01,105.97 133.86,103.12 133.86,102.11 140.84,95.12 141.6,95.12 142.62,94.11 146.69,94.11 146.94,94.36 146.94,94.69 146.69,94.95 R138.2 R137.2
  BOTTOM w0.381: TINY210.C6 117.34,58 109.84,65.5 109.84,80.52 105.16,85.2 105.16,96.14 104.65,96.65 v1(104.65,103) 102.22,105.42 102.22,107.17 100.24,109.15 99.47,109.15 88.08,120.54 87.65,120.97 87.65,123.57 CAMERA.6
XCIPCLK: length 143.6
  TOP w0.203: U9.9 152.37,106.78 152.65,107.06 152.86,107.06 152.99,106.93 154.43,106.93 154.94,107.44 154.94,109.35 154.7,109.59 148.37,109.59 147.1,108.32 138.65,108.32 130.14,116.83 112.97,116.83 107.65,111.51 v1(107.31,111.51)
  BOTTOM w0.203: CAMERA.8 89.57,123.65 89.57,122.02 94.52,117.06 101.12,117.06 106.32,111.86 107.08,111.86 107.31,111.63 v1(107.31,111.51) 108.08,110.74 109.09,110.74 110.07,109.77 110.07,104.51 107.96,102.41 107.96,85.69 111.66,82 111.66,67.17 118.82,60 TINY210.C8
XCIVSYNC: length 127.3
  TOP w0.203: v1(135.03,103.28) 135.03,103.66 131.92,106.76 111.55,106.76 v1(108.97,109.35) ; U9.24 146.64,100.87 v1(145.97,100.2)
  BOTTOM w0.203: v1(135.03,103.28) 135.15,103.15 143.1,103.15 145.97,100.28 v1(145.97,100.2) ; CAMERA.7 88.67,122.35 94.36,116.67 100.76,116.67 107.26,110.16 108.15,110.16 v1(108.97,109.35) 109.68,108.64 109.68,105.43 109.5,105.25 109.5,104.5 107.57,102.57 107.57,85.53 111.25,81.85 111.25,66.45 118.62,59.09 120.09,59.09 TINY210.C7
XCIYDATA0: length 108.3
  TOP w0.203: v1(115.45,108.82) 115.84,109.22 118.87,109.22 119.85,108.25 133.99,108.25 138.18,104.06 146.04,104.06 146.24,103.87 U9.18
  BOTTOM w0.203: TINY210.C16 118.36,68 115.85,70.51 115.85,84.12 112.19,87.77 112.19,98.26 112.19,99.82 114.71,102.34 114.71,108.1 115.42,108.82 115.44,108.82 v1(115.45,108.82) 115.82,109.2 115.82,112 110.15,117.67 109.69,118.14 106.04,118.14 103.21,120.96 98.6,120.96 97.66,121.89 97.66,123.56 CAMERA.16
XCIYDATA1: length 113.3
  TOP w0.203: U9.17 146.54,104.37 146.45,104.46 138.37,104.46 128.75,114.07 119.53,114.07 115.3,109.84 v1(115.06,109.84)
  BOTTOM w0.203: TINY210.C15 120.96,68 120.04,67.09 118.62,67.09 115.42,70.29 115.42,83.99 111.8,87.61 111.8,98.42 111.8,99.99 114.31,102.5 114.31,109.09 v1(115.06,109.84) 115.2,109.98 115.2,112.07 109.53,117.74 105.87,117.74 103.05,120.57 97.95,120.57 96.67,121.85 CAMERA.15
XCIYDATA2: length 118
  TOP w0.203: v1(114.17,110.11) 114.3,110.24 114.52,110.24 118.75,114.47 128.99,114.47 138.61,104.85 146.56,104.85 146.64,104.93 148.49,104.93 148.87,105.31 U9.16
  BOTTOM w0.203: CAMERA.14 95.63,123.59 95.63,122.05 97.5,120.17 102.89,120.17 105.71,117.35 109.37,117.35 114.68,112.03 114.68,110.62 v1(114.17,110.11) 113.92,109.86 113.92,102.66 111.35,100.1 111.35,98.06 111.4,98.01 111.4,87.45 115.02,83.83 115.02,69.98 TINY210.C14
XCIYDATA3: length 120.9
  TOP w0.203: U9.15 149.37,106.66 148.97,107.06 148.63,107.06 147.92,106.35 147.5,106.35 146.4,105.24 138.94,105.24 129.32,114.86 118.54,114.86 114.55,110.87 113.92,110.87 v1(113.79,111)
  BOTTOM w0.203: TINY210.C13 120.09,65.09 118.62,65.09 114.63,69.08 114.63,83.67 111.01,87.29 111.01,97.85 110.96,97.9 110.96,100.26 113.42,102.73 113.42,110.63 v1(113.79,111) 113.92,111.12 113.92,112.24 109.2,116.95 105.55,116.95 102.72,119.78 97.14,119.78 94.67,122.24 CAMERA.13
XCIYDATA4: length 123.6
  TOP w0.203: U9.14 149.87,106.92 149.22,107.57 148.58,107.57 147.75,106.74 147.34,106.74 146.24,105.64 139.1,105.64 129.49,115.25 118.38,115.25 115.14,112.01 113.28,112.01 v1(113.03,111.76)
  BOTTOM w0.203: TINY210.C12 114.22,68.78 114.22,83.52 110.57,87.17 110.57,97.08 110.62,97.14 110.62,97.68 110.57,97.73 110.57,101.04 113.03,103.5 v1(113.03,111.76) 113.03,112.57 109.04,116.56 108.02,116.56 105.39,116.56 102.56,119.39 96.51,119.39 93.73,122.17 93.73,123.49 CAMERA.12
XCIYDATA5: length 128.4
  TOP w0.203: v1(111.25,111) 111.25,111.12 113.79,113.66 114.89,113.66 116.87,115.65 129.65,115.65 139.26,106.03 146.07,106.03 147.18,107.14 147.59,107.14 148.53,108.08 149.61,108.08 150.37,107.31 U9.13
  BOTTOM w0.203: CAMERA.11 92.67,121.07 95.5,118.24 102.09,118.24 104.91,115.42 107.47,115.42 111.25,111.63 v1(111.25,111) 111.25,104.03 109.14,101.92 109.14,86.18 112.88,82.45 112.88,67.67 117.46,63.09 120.09,63.09 TINY210.C11
XCIYDATA6: length 131
  TOP w0.203: U9.12 150.87,107.45 149.85,108.47 148.37,108.47 147.43,107.53 147.02,107.53 145.91,106.43 139.43,106.43 129.81,116.04 116.71,116.04 114.73,114.06 113.63,114.06 111.33,111.76 110.49,111.76 110.34,111.61 v1(110.21,111.61)
  BOTTOM w0.203: TINY210.C10 117.97,62 112.47,67.5 112.47,82.3 108.75,86.02 108.75,102.08 110.86,104.19 110.86,110.46 110.21,111.1 v1(110.21,111.61) 106.8,115.02 104.75,115.02 101.92,117.85 95.34,117.85 91.69,121.49 91.69,123.53 CAMERA.10
XCIYDATA7: length 133.8
  TOP w0.203: U9.11 151.37,107.58 150.09,108.86 148.2,108.86 147.27,107.92 146.63,107.92 145.9,107.19 R139.2 143.81,107.92 138.48,107.92 129.98,116.43 113.51,116.43 v1(108.77,111.69)
  BOTTOM w0.203: TINY210.C9 120.09,61.09 118.31,61.09 112.06,67.33 112.06,82.15 108.36,85.86 108.36,102.24 110.46,104.35 110.46,110 v1(108.77,111.69) 107.28,113.18 105.77,113.18 101.49,117.46 94.89,117.46 90.67,121.67 CAMERA.9
XEINT6_SD0_NWP: length 45.7
  TOP w0.203: v1(152.15,80.11) 151.81,79.77 151.21,79.17 151.21,66.64 145.15,60.58 143.55,60.58 143.4,60.43 142.72,60.43 v1(142.24,59.94)
  BOTTOM w0.203: TINY210.B24 142.09,46.09 142.09,59.79 v1(142.24,59.94) ; v1(152.15,80.11) 152.15,81.64 151.7,82.08 ; 151.7,82.08 151.68,82.1 150.45,82.1 ; 151.7,82.08 CON10.10
XEINT7: length 21
  TOP w0.203: U4.34 165.76,38.12 164.73,39.15 164.73,43.8 163.91,44.62 163.91,47.38 162.82,48.48 159.22,48.48 157.99,47.24 157.99,45.99 TINY210.B40
XEINT9: length 135
  TOP w0.203: SDIO.16 68.7,97.39 68.7,92.51 R28.2 70.1,91.11 70.1,88.39 72.01,86.49 v1(72.01,86.36)
  BOTTOM w0.203: v1(72.01,86.36) 72.01,86.23 74.04,84.2 97.41,84.2 103.61,78 103.61,74.29 104.53,73.36 104.53,52.38 103.23,51.07 103.23,46.89 111.12,38.99 126.28,38.99 128.4,41.11 129.47,41.11 130.78,42.42 135.89,42.42 136.31,42.84 136.65,43.18 146.46,43.18 146.5,43.22 150.28,43.22 151,43.94 TINY210.B34
XEINT10: length 174.4
  TOP w0.203: LCD4.31 11.95,84.88 18.14,78.69 18.14,73.05 22.95,68.24 39.16,68.24 42.53,64.87 42.71,64.87 v1(43.97,63.61) 44.21,63.37 70.74,63.37 85.56,78.19 91.54,78.19 91.75,77.98 LCD2.31 94.84,77.98 96,79.14 96,81.2 102.25,87.46 102.8,87.46 105.75,90.4 113.67,90.4 115.98,92.71 121.54,92.71 v1(122.3,93.47)
  BOTTOM w0.203: TINY210.A22 139.91,89.91 139.91,91.48 138.52,92.88 122.9,92.88 v1(122.3,93.47) ; LCD3.31 43.82,66 43.97,65.85 v1(43.97,63.61) 43.97,62.44 43.92,62.39 43.92,53.01 43.82,52.91 LCD1.31
XEINT11: length 172.4
  TOP w0.203: TINY210.A46 163,76.77 156.08,69.85 156.08,66.8 147.45,58.17 125.09,58.17 124.07,57.14 118.47,57.14 117.72,56.39 91.98,56.39 79.15,43.56 v1(60.45,43.56) ; U7.5 v1(61.74,82.42) 61.82,82.51 R30.2
  BOTTOM w0.203: v1(60.45,43.56) 59.82,44.2 59.82,73.79 61.34,75.31 61.34,82.03 v1(61.74,82.42)
XEINT14: length 174.6
  TOP w0.203: LCD4.43 11.03,96.88 10.14,95.99 8.99,95.99 8.26,95.25 8.26,92.71 8.44,92.52 8.44,92.51 9.18,91.77 9.95,91.77 9.96,91.76 11.22,91.76 11.22,91.77 11.95,91.77 12.7,91.02 12.7,90.73 22.67,80.76 27.57,80.76 31.31,77.03 31.31,73.46 32.38,72.39 51.87,72.39 v1(54.25,70) ; v1(50.04,46.48) 51.69,46.48 52.67,45.5 76.8,45.5 89.72,58.42 95.91,58.42 96.53,59.04 96.53,62.29 99,64.76 99,65.9 99.35,66.25 100.67,67.57 107.57,67.57 109.16,69.15 112.48,69.15 116.65,73.32 116.65,73.98 118.67,76 TINY210.C24
  BOTTOM w0.203: v1(50.04,46.48) 49.82,46.7 LCD1.43 49.82,58.17 54.25,62.6 v1(54.25,70)
XEINT15: length 172.6
  TOP w0.203: v1(13.46,92.33) 14.09,91.71 14.09,90.01 22.94,81.15 28.7,81.15 30.99,78.87 43.81,78.87 45.34,77.34 50.42,77.34 55.12,72.64 v1(55.24,72.64) ; TINY210.C22 118.83,74 118.12,73.29 117.77,73.29 112.82,68.34 109.49,68.34 107.51,66.36 102.01,66.36 101.78,66.59 100.8,66.59 99.79,65.58 99.79,64.43 97.32,61.96 97.32,58.71 96.24,57.63 90.05,57.63 77.13,44.72 51.55,44.72 v1(51.18,45.09)
  BOTTOM w0.203: v1(13.46,92.33) 13.46,96.27 11.85,97.87 10.58,97.87 LCD4.44 ; v1(55.24,72.64) 54.91,72.31 54.91,62.59 50.32,57.99 LCD1.44 50.32,47.85 50.83,47.35 50.83,45.44 v1(51.18,45.09)
XEINT16/KP_COL0: length 261.7
  TOP w0.203: TINY210.A53 170.09,90.09 170.09,84.22 166.32,80.45 166.32,76.48 147.52,57.68 125.5,57.68 122.95,55.14 118.14,55.14 117.39,55.88 92.03,55.88 78.95,42.8 29.34,42.8 20.95,51.18 R35.1 18.86,50.48 10.35,50.48 v1(10.03,50.8)
  BOTTOM w0.203: K1.1 7.37,93.02 7.37,53.47 v1(10.03,50.8) 11.94,48.9 11.94,39.18 10.29,37.54 10.29,36.58 6.56,32.85 CON7.1
XEINT17/KP_COL1: length 253.1
  TOP w0.203: v1(10.03,49.66) 10.79,48.9 18.8,48.9 R37.1 20.95,49.66 28.21,42.41 79.11,42.41 92.14,55.44 92.79,55.44 112.6,55.44 115.07,52.96 121.82,52.96 126.14,57.28 147.69,57.28 166.73,76.32 166.73,80.28 170.56,84.12 170.56,88.56 TINY210.A54
  BOTTOM w0.203: K2.1 6.96,87.07 6.96,52.73 v1(10.03,49.66) 11.18,48.51 11.18,38.97 9.9,37.7 9.9,37.08 7.67,34.85 CON7.2
XEINT18/KP_COL2: length 247.4
  TOP w0.203: TINY210.A55 172.09,90.09 172.09,85.07 167.51,80.5 167.51,76.53 147.85,56.87 128.75,56.87 124.21,52.32 115.15,52.32 112.44,55.04 92.3,55.04 79.27,42.01 27.08,42.01 20.95,48.13 R39.1 18.86,47.43 11.11,47.43 v1(10.03,48.51)
  BOTTOM w0.203: CON7.3 7.64,36.85 10.67,39.88 10.67,47.88 v1(10.03,48.51) 6.57,51.98 6.57,81.12 K3.1
XEINT19/KP_COL3: length 236.6
  TOP w0.203: v1(10.01,47.37) 11.53,45.85 18.8,45.85 R40.1 20.95,46.61 25.95,41.62 79.43,41.62 92.46,54.65 112.27,54.65 114.99,51.93 124.37,51.93 128.8,56.36 147.92,56.36 167.95,76.39 167.95,80.36 172.47,84.87 172.47,84.89 172.59,85.02 172.59,88.59 TINY210.A56
  BOTTOM w0.203: CON7.4 7.35,38.85 10.01,41.5 v1(10.01,47.37) 10.01,47.61 6.17,51.44 6.17,75.16 K4.1
XEINT24/KP_ROW0: length 233.2
  TOP w0.203: v1(9.35,46.1) 11.13,44.32 18.8,44.32 R43.2 21.34,45.09 25.2,41.22 79.6,41.22 91.61,53.24 113.13,53.24 115.06,51.31 126.35,51.31 129.81,54.78 150.32,54.78 170.76,75.22 170.76,81.74 174.65,85.63 174.65,88.06 174.09,88.62 174.09,90.09 TINY210.A57
  BOTTOM w0.203: CON7.5 7.32,40.85 9.35,42.88 v1(9.35,46.1) 9.35,47.71 5.78,51.28 5.78,69.2 K5.1
XEINT25/KP_ROW1: length 222.7
  TOP w0.203: v1(8.69,43.69) 8.76,43.69 9.65,42.8 18.8,42.8 R64.2 21.34,43.56 24.07,40.83 79.76,40.83 91.77,52.84 112.96,52.84 114.89,50.91 126.51,50.91 129.98,54.38 150.51,54.38 171.17,75.05 171.17,81.58 175.06,85.46 175.06,88.94 TINY210.A58
  BOTTOM w0.203: K6.1 5.38,63.25 5.38,51.11 8.69,47.81 v1(8.69,43.69) 8.43,43.94 7.16,43.94 6.07,42.85 CON7.6
XEINT26/KP_ROW2: length 219.5
  TOP w0.203: TINY210.A59 175.91,89.91 175.91,85.74 171.58,81.41 171.58,74.88 150.69,53.99 130.14,53.99 126.67,50.52 114.73,50.52 112.8,52.45 91.94,52.45 79.92,40.44 22.58,40.44 20.98,42.04 R65.2 18.8,41.27 10.03,41.27 8,43.31 v1(8,45.59)
  BOTTOM w0.203: CON7.7 7.26,44.85 v1(8,45.59) 8,47.81 4.99,50.82 4.99,57.29 K7.1
XEINT27/KP_ROW3: length 209.8
  TOP w0.203: CON7.8 5.97,46.85 7.34,45.48 7.34,43.33 11.18,39.5 18.54,39.5 R66.2 20.03,40.04 80.09,40.04 92.1,52.06 112.64,52.06 114.57,50.13 126.84,50.13 130.3,53.59 150.87,53.59 172.09,74.81 172.09,81.28 176.32,85.52 176.32,88.32 TINY210.A60
  BOTTOM w0.203: K8.1 3.83,48.35 CON7.8
XI2CSCL0: length 165.9
  TOP w0.203: v1(104.57,51.36) 104.37,51.56 97.26,51.56 R9.2 94.74,49.05 U5.6 94.74,44.7 93.87,43.83 86.12,43.83 80.9,38.61 60.66,38.61 60.17,38.13 v1(59.49,38.13) ; R57.1 R31.1 R127.1 131.32,40.51 129.67,42.16 v1(129.03,42.16) ; U7.6 61.74,77.87 61.59,77.72 60.96,77.72 60.58,78.11 v1(60.58,78.49) 60.58,87.25 59.31,88.52 59.31,96 SDIO.5
  BOTTOM w0.203: v1(104.57,51.36) 104.55,51.33 104.55,46.73 111.32,39.95 125.42,39.95 126.21,40.74 126.21,40.79 126.6,41.17 126.64,41.17 127.53,42.06 128.93,42.06 v1(129.03,42.16) 130.07,43.21 131.1,43.21 135,43.21 135.99,44.2 135.99,45.29 137,46.3 TINY210.B19 ; v1(60.58,78.49) 60.45,78.36 60.45,75.44 59.31,74.3 59.31,38.31 v1(59.49,38.13)
XI2CSCL2/IEM_SPWI: length 182.3
  TOP w0.203: LCD4.41 11.93,94.88 14.99,91.82 25.53,91.82 27.3,90.04 46.31,90.04 50.12,93.85 v1(52.58,93.85) ; v1(48.64,46.35) 49.17,45.82 51.49,45.82 52.2,45.11 76.97,45.11 89.88,58.03 96.07,58.03 96.92,58.87 96.92,62.12 99.39,64.6 99.39,65.74 99.63,65.98 100.52,66.86 100.83,67.17 107.77,67.17 109.33,68.74 112.66,68.74 117.46,73.55 117.46,73.69 118.64,74.86 119.08,74.86 120.22,76 TINY210.C23
  BOTTOM w0.203: v1(48.64,46.35) 48.64,47.12 48.82,47.29 LCD1.41 48.82,58.98 52.96,63.12 52.96,93.47 v1(52.58,93.85)
XI2CSDA0: length 171.5
  TOP w0.203: v1(58.42,37.47) 60.07,37.47 60.82,38.21 81.06,38.21 86.28,43.43 94.87,43.43 96.01,44.58 U5.5 96.01,47.88 96.49,48.36 R10.2 97.19,49.97 103.7,49.97 v1(103.89,49.78) ; R58.1 R126.1 R32.1 131.3,38.99 130.6,38.29 128.97,38.29 126.87,40.39 v1(126.87,40.51) ; U7.7 62.24,77.73 61.72,77.22 60.58,77.22 59.56,78.23 v1(59.56,78.49) 60.07,78.99 60.07,86.9 58.71,88.27 58.71,96.65 59.59,97.54 SDIO.6
  BOTTOM w0.203: v1(103.89,49.78) 103.89,46.83 111.16,39.56 125.92,39.56 v1(126.87,40.51) 127.86,41.5 129.31,41.5 130.61,42.81 135.22,42.81 137,44.59 TINY210.B20 ; v1(59.56,78.49) 59.82,78.23 59.82,75.48 58.83,74.49 58.83,37.88 v1(58.42,37.47)
XI2CSDA2/IEM_SCLK: length 186
  TOP w0.203: v1(49.78,44.96) 50.42,44.32 77.29,44.32 90.21,57.24 96.4,57.24 97.71,58.55 97.71,61.8 100.2,64.29 100.2,65.41 100.99,66.19 101.62,66.19 101.92,65.89 107.67,65.89 109.68,67.89 113,67.89 118.01,72.9 119.38,72.9 120.48,74 TINY210.C21 ; LCD4.42 10.48,95.77 11.95,95.77 15.39,92.33 25.91,92.33 27.69,90.55 46.1,90.55 50.16,94.61 52.96,94.61 v1(53.59,93.98)
  BOTTOM w0.203: v1(49.78,44.96) 49.32,45.42 LCD1.42 49.32,58.55 53.59,62.82 v1(53.59,93.98)
XM0ADDR2: length 18.5
  TOP w0.203: TINY210.B37 156.3,48.3 158.05,48.3 158.62,48.87 164.42,48.87 165.91,47.38 165.91,42.09 165.74,41.91 R7.2
XM0CSN1: length 20.1
  TOP w0.203: U4.37 163.91,35.14 164.19,35.42 164.19,35.7 163.96,35.94 v1(163.07,35.94) ; v1(157.48,36.22) 157.48,36.7 156.08,38.1 156.08,45.59 157,46.51 TINY210.B39
  BOTTOM w0.203: v1(157.48,36.22) 162.79,36.22 v1(163.07,35.94)
XM0DATA0: length 23.8
  TOP w0.203: U4.18 171.19,32.14 169.8,33.53 166.62,33.53 v1(166.5,33.66)
  BOTTOM w0.203: TINY210.B45 163,46.31 162.09,45.4 162.09,44.62 163.5,43.21 165.21,43.21 168.02,40.4 168.02,35.18 v1(166.5,33.66)
XM0DATA1: length 21.9
  TOP w0.203: v1(166.37,32.75) 169.82,32.75 170.93,31.63 U4.17
  BOTTOM w0.203: v1(166.37,32.75) 166.53,32.75 167.16,33.38 167.16,33.76 168.41,35.02 168.41,40.56 165.36,43.61 164.39,43.61 TINY210.B46
XM0DATA2: length 23.3
  TOP w0.203: v1(167.26,32.09) 169.92,32.09 170.87,31.14 U4.16
  BOTTOM w0.203: v1(167.26,32.09) 167.26,32.26 167.56,32.56 167.56,33.61 168.81,34.85 168.81,40.72 165.51,44.02 164.69,44.02 164.09,44.62 164.09,46.09 TINY210.B47
XM0DATA3: length 21.1
  TOP w0.203: v1(167.59,31.24) 167.85,31.5 169.8,31.5 171.16,30.14 U4.14
  BOTTOM w0.203: TINY210.B48 165.09,45 169.2,40.89 169.2,34.69 167.97,33.46 167.97,32.7 167.96,32.69 167.96,31.61 v1(167.59,31.24)
XM0DATA4: length 26
  TOP w0.203: v1(172.85,28.32) 172.85,29.21 172.42,29.63 U4.13
  BOTTOM w0.203: TINY210.B49 167,46.36 168.05,45.31 168.05,43.15 169.99,41.21 169.99,34.36 168.78,33.16 168.78,29.34 169.67,28.45 172.72,28.45 v1(172.85,28.32)
XM0DATA5: length 23
  TOP w0.203: v1(171.32,27.18) 170.56,27.18 170.26,27.48 U4.12
  BOTTOM w0.203: TINY210.B50 167,43.64 169.6,41.05 169.6,34.53 168.36,33.29 168.36,29.12 169.8,27.69 170.81,27.69 v1(171.32,27.18)
XM0DATA6: length 20.4
  TOP w0.203: v1(169.93,29.34) 169.76,29.17 U4.11
  BOTTOM w0.203: v1(169.93,29.34) 170.14,29.55 170.14,30.86 170.14,30.86 170.14,31.41 170.14,31.41 170.14,33.4 170.78,34.04 170.78,41.56 169.54,42.79 169.54,44.32 169.86,44.64 169.86,45.43 169,46.29 TINY210.B51
XM0DATA7: length 18
  TOP w0.203: U4.10 169.26,29.95 v1(169.44,30.13)
  BOTTOM w0.203: v1(169.44,30.13) 169.57,30.25 169.57,33.38 170.38,34.2 170.38,41.39 169,42.78 TINY210.B52
XM0DATA8: length 13.3
  TOP w0.203: TINY210.B53 169.91,45.91 169.91,44.58 169.09,43.76 167.71,43.76 166.47,42.52 166.47,38.76 167.26,37.97 U4.31
XM0DATA9: length 9.7
  TOP w0.203: U4.29 168.26,38.01 171.35,41.1 171.35,44.65 TINY210.B54
XM0DATA10: length 12
  TOP w0.203: U4.28 168.76,37.95 171.74,40.93 171.74,43.54 172.09,43.88 172.09,46.09 TINY210.B55
XM0DATA11: length 9.8
  TOP w0.203: TINY210.B56 173,44.17 172.14,43.3 172.14,40.61 169.26,37.74 U4.27
XM0DATA12: length 12.5
  TOP w0.203: TINY210.B57 173.91,45.91 173.91,44.51 172.54,43.14 172.54,40.46 169.76,37.68 U4.26
XM0DATA13: length 10.3
  TOP w0.203: TINY210.B58 173.1,43.1 173.1,40.13 170.26,37.29 U4.25
XM0DATA14: length 14.4
  TOP w0.203: U4.24 172.59,35.14 172.97,35.52 172.97,38.23 174.24,39.5 174.24,41.91 175.91,43.58 175.91,45.91 TINY210.B59
XM0DATA15: length 14.7
  TOP w0.203: TINY210.B60 177.42,44.58 177.42,37.47 174.08,34.14 U4.22
XM0OEN: length 10.1
  TOP w0.203: TINY210.B44 161,43.47 164.34,40.13 164.34,38.99 165.26,38.06 U4.35
XM0WEN: length 12.6
  TOP w0.203: U4.36 164.76,37.68 163.7,38.73 163.7,40.21 160.09,43.83 160.09,46.09 TINY210.B43
XMMC0CDN: length 32.6
  BOTTOM w0.203: TINY210.B23 140.44,47.56 140.44,59.51 144.67,63.74 151.33,63.74 151.68,64.09 151.68,65.64 151.03,66.29 CON10.11 146.97,66.29 R71.1
XMMC0DATA0: length 45.9
  TOP w0.203: v1(152.27,77.04) 152.83,76.49 152.83,67.69 145.17,60.03 143.51,60.03 v1(143.25,59.77)
  BOTTOM w0.203: TINY210.B25 143,50.54 142.65,50.89 142.65,59.16 v1(143.25,59.77) ; R73.1 147.48,70.99 148.72,72.23 148.72,76.33 149.41,77.02 CON10.7 152.25,77.02 v1(152.27,77.04)
XMMC0DATA1: length 50.2
  TOP w0.203: v1(152.07,78.74) 153.23,77.58 153.23,67.52 145.09,59.37 v1(144.4,59.37)
  BOTTOM w0.203: v1(144.4,59.37) 143.83,59.37 143.05,58.6 143.05,51.06 143.64,50.48 143.64,47.75 143.91,47.47 143.91,45.91 TINY210.B26 ; R72.1 146.84,76.73 148.82,78.72 CON10.8 152.05,78.72 v1(152.07,78.74)
XMMC0DATA2: length 20.9
  BOTTOM w0.203: TINY210.B27 144.12,47.88 144.12,50.57 143.46,51.23 143.46,56.28 146.4,59.22 146.4,61.03 R74.1 148.7,59.6 CON10.9
XMMC0DATA3: length 29.5
  BOTTOM w0.203: TINY210.B28 145.91,45.91 145.91,47.61 144.68,48.84 144.68,50.58 143.87,51.4 143.87,55.77 146.39,58.29 150.96,58.29 151.72,59.05 151.72,62.14 CON10.1 147.69,62.14 R38.1
XMMC2CDN/SPI_MISO2: length 111.5
  TOP w0.203: SDIO.15 70.23,95.65 70.23,93.24 70.89,92.58 R14.1 71.63,91.11 71.63,88.14 73.15,86.61 79.31,86.61 80.81,88.11 80.81,88.65 85.12,92.96 96.04,92.96 101.15,98.07 111.44,98.07 113.79,100.42 123.92,100.42 123.95,100.46 v1(124.28,100.46)
  BOTTOM w0.203: v1(124.28,100.46) 124.8,100.46 125.09,100.16 142.77,100.16 145.04,97.89 156.77,97.89 156.81,97.85 157.02,97.85 163,91.87 TINY210.A45
XMMC2CLK/SPI_CLK2: length 111.6
  TOP w0.203: SDIO.13 68.2,95.68 68.2,92.2 R13.1 68.54,91.15 68.54,88.43 71.35,85.62 79.53,85.62 81.48,87.58 82.37,87.58 86.12,91.33 96.53,91.33 101.96,96.75 112.48,96.75 114.37,98.65 121.53,98.65 122.12,99.24 125.02,99.24 v1(125.63,98.63)
  BOTTOM w0.203: v1(125.63,98.63) 125.9,98.36 142.4,98.36 144.41,96.35 156.14,96.35 156.33,96.16 156.54,96.16 161,91.7 TINY210.A43
XMMC2CMD/SPI_CSN2: length 119
  TOP w0.203: SDIO.14 66.7,97.39 66.7,96.04 66.32,95.66 R23.2 67.06,91.11 67.06,88.52 70.47,85.1 79.56,85.1 81.62,87.16 82.51,87.16 86.28,90.93 96.7,90.93 102.12,96.35 112.64,96.35 112.89,96.61 114.54,98.25 121.69,98.25 122.28,98.84 123.43,98.84 v1(123.7,98.58)
  BOTTOM w0.203: v1(123.7,98.58) 124.41,99.29 125.91,99.29 126.44,98.76 142.56,98.76 144.57,96.75 156.3,96.75 156.49,96.56 156.7,96.56 161.91,91.34 161.91,89.91 TINY210.A44
XMMC2DATA0/SPI_MOSI2: length 110.1
  TOP w0.203: SDIO.17 71.59,96.28 71.59,95.79 73.94,93.45 R18.1 74.64,91.15 74.64,88.65 75.65,87.63 79.21,87.63 80.02,88.44 80.02,88.98 84.87,93.83 94.92,93.83 95.58,93.83 100.61,98.86 111.11,98.86 113.47,101.21 123.18,101.21 123.49,101.52 125.3,101.52 v1(125.35,101.47)
  BOTTOM w0.203: TINY210.A47 164.47,91.53 163.9,91.53 157.59,97.84 157.26,98.17 157.18,98.25 156.98,98.25 156.94,98.29 145.21,98.29 142.93,100.56 126.59,100.56 125.68,101.47 v1(125.35,101.47)
XMMC2DATA1: length 119.1
  TOP w0.203: v1(126.62,101.47) 125.96,100.81 125.04,100.81 124.73,101.12 123.67,101.12 123.37,100.82 113.63,100.82 111.27,98.46 100.77,98.46 95.74,93.43 94.76,93.43 85.04,93.43 80.42,88.81 80.42,88.27 79.26,87.12 73.76,87.12 73.15,87.73 73.15,91.11 R34.2 70.7,93.56 70.7,97.39 SDIO.18
  BOTTOM w0.203: TINY210.A48 165.91,89.91 165.91,91.31 165.3,91.92 164.07,91.92 157.75,98.23 157.52,98.46 157.35,98.64 157.14,98.64 157.1,98.68 145.37,98.68 142.17,101.88 141.1,101.88 140.21,100.99 127.1,100.99 v1(126.62,101.47)
XMMC2DATA2: length 107.1
  TOP w0.203: v1(124.49,102.59) 124.23,102.34 123.16,102.34 122.83,102 113.14,102 110.78,99.64 100.28,99.64 95.25,94.61 84.45,94.61 81.69,91.85 R19.1 73.59,95.24 SDIO.19
  BOTTOM w0.203: TINY210.A49 167,91.78 166.46,92.32 164.23,92.32 157.92,98.63 157.61,98.93 157.51,99.03 157.3,99.03 157.26,99.07 145.53,99.07 142.33,102.27 140.93,102.27 140.04,101.38 127.64,101.38 126.89,102.13 124.94,102.13 v1(124.49,102.59) ; SDIO.19 73.59,95.44
XMMC2DATA3: length 118.1
  TOP w0.203: v1(126.36,102.79) 125.98,102.79 125.35,102.16 125.02,102.16 124.78,101.92 123.33,101.92 123.02,101.61 113.3,101.61 110.95,99.25 100.44,99.25 95.41,94.22 84.71,94.22 79.63,89.14 79.63,88.6 79.14,88.11 76.71,88.11 76.2,88.63 76.2,91.11 R60.2 75.46,92.68 72.64,95.5 72.64,97.33 SDIO.20
  BOTTOM w0.203: TINY210.A50 167.91,89.91 167.91,91.42 166.62,92.71 164.39,92.71 157.63,99.47 145.7,99.47 143.49,101.67 142.5,102.67 140.51,102.67 139.62,101.78 127.84,101.78 126.87,102.74 126.42,102.74 v1(126.36,102.79)
